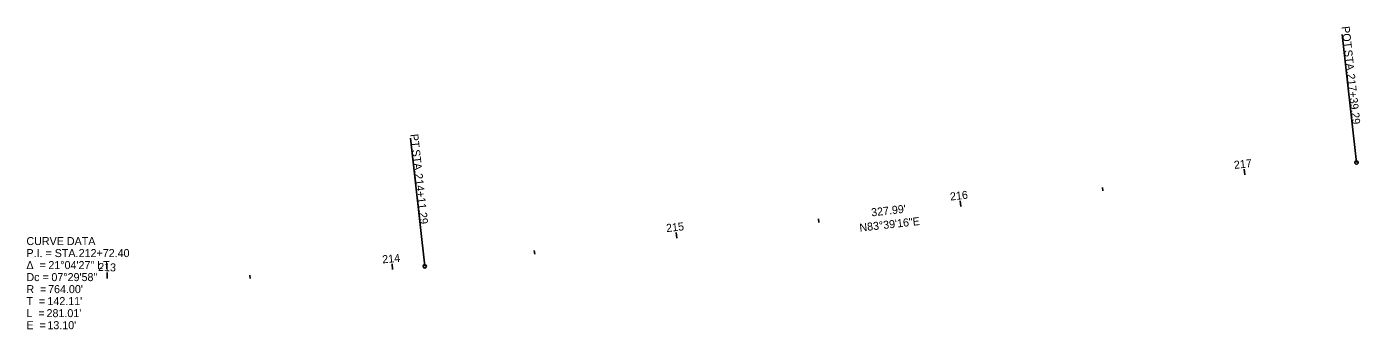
# Model space of a CAD drawing. Extents: x 1600023 to 1602131, y 285824 to 287284.
# Drawn here: x 1601638.4 to 1602105, y 286706.8 to 286812.6 of the extents above; entities that cross this region are included whole.
import ezdxf

# ---------------------------------------------------------------- set-up
doc = ezdxf.new("R2010")
doc.units = 0
for name, color, linetype in [('PM_P_CL_Double_Solid', 7, 'Continuous'), ('PM_P_Dotted_Line', 7, 'Continuous'), ('PM_P_Edge_Line', 7, 'Continuous'), ('PM_P_Transverse_Line', 7, 'Continuous'), ('PM_P_Yield_Line', 7, 'Continuous')]:
    doc.layers.add(name, color=color, linetype=linetype)

msp = doc.modelspace()

# ---------------------------------------------------------------- linework, layer by layer
at = {"layer": 'PM_P_CL_Double_Solid'}
for p, q in [((1602103.63, 286765.08), (1602098.66, 286809.8)), ((1601777.65, 286728.82), (1601772.68, 286773.55))]:
    msp.add_line(p, q, dxfattribs=at)
for centre in [(1602103.63, 286765.08), (1601777.65, 286728.82)]:
    msp.add_circle(centre, 0.6, dxfattribs=at)
at = {"layer": 'PM_P_Transverse_Line'}
for p, q in [((1602064.59, 286760.73), (1602064.37, 286762.72)), ((1602014.89, 286755.21), (1602014.76, 286756.4)), ((1601965.2, 286749.68), (1601964.98, 286751.67)), ((1601915.51, 286744.16), (1601915.37, 286745.35)), ((1601865.81, 286738.63), (1601865.59, 286740.62)), ((1601816.12, 286733.1), (1601815.99, 286734.3)), ((1601766.42, 286727.66), (1601766.22, 286729.65)), ((1601666.53, 286724.61), (1601666.6, 286726.61)), ((1601716.53, 286724.5), (1601716.49, 286725.7))]:
    msp.add_line(p, q, dxfattribs=at)

# ---------------------------------------------------------------- texts
at = {"layer": 'PM_P_CL_Double_Solid'}
for s, p in [('POT', (1602098.4, 286812.56)), (' STA. ', (1602099.19, 286805.4)), ('217+39.29', (1602100.24, 286796.01)), ('PT', (1601772.57, 286774.92)), (' STA. ', (1601773.05, 286770.54)), ('214+11.29', (1601774.1, 286761.14))]:
    msp.add_text(s, height=2.8, rotation=276.3456, dxfattribs=at).set_placement(p)
at = {"layer": 'PM_P_Dotted_Line'}
msp.add_text("327.99'", height=2.8, rotation=6.3456, dxfattribs=at).set_placement((1601934, 286746.25))
at = {"layer": 'PM_P_Edge_Line'}
msp.add_text('N83°39\'16"E', height=2.8, rotation=6.3456, dxfattribs=at).set_placement((1601929.88, 286740.92))
at = {"layer": 'PM_P_Transverse_Line'}
for s, rotation, p in [('217', 6.3456, (1602060.92, 286762.84)), ('216', 6.3456, (1601961.59, 286751.79)), ('215', 6.3456, (1601862.25, 286740.75)), ('214', 5.4985, (1601762.92, 286729.83)), ('213', 357.9991, (1601663.35, 286727.22))]:
    msp.add_text(s, height=2.8, rotation=rotation, dxfattribs=at).set_placement(p)
at = {"layer": 'PM_P_Yield_Line'}
for s, p in [('CURVE DATA', (1601638.31, 286736.24)), ('P.I. = STA. ', (1601638.31, 286732.04)), ('212+72.40', (1601656.58, 286732.04)), ('Δ  = ', (1601638.31, 286727.84)), ('21°04\'27" LT', (1601645.99, 286727.84)), ('Dc = ', (1601638.31, 286723.64)), ('07°29\'58"', (1601647.05, 286723.64)), ('R  = ', (1601638.31, 286719.44)), ("764.00'", (1601645.89, 286719.44)), ('T  = ', (1601638.31, 286715.24)), ('L  = ', (1601638.31, 286711.04)), ("281.01'", (1601645.35, 286711.04)), ("142.11'", (1601645.65, 286715.24)), ('E  = ', (1601638.31, 286706.84)), ("13.10'", (1601645.65, 286706.84))]:
    msp.add_text(s, height=2.8, dxfattribs=at).set_placement(p)

doc.saveas('drawing.dxf')
